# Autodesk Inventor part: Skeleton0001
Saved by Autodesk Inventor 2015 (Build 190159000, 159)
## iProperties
Created: 2015-05
Part Number: Skeleton0001
Material: Generic
Document SubType Name: Modeling
Designer: TREINA6
Density: 1 g/cm^3
Appearance: Default
_SkeletonDoc: Frame Skeleton File
_Version: 15.0.0
Author: TREINA6
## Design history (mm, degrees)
sketch "Reference Skeleton"
